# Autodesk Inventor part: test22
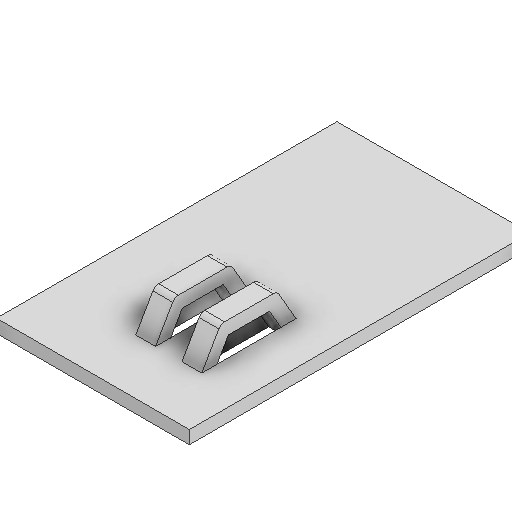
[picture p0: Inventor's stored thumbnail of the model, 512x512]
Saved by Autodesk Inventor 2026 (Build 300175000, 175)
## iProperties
Created: 2025-08
Part Number: test22
Material: Generic
Document SubType Name: Sheet Metal
Designer: sup1
Density: 1 g/cm^3
Sheet Metal Rule: Default
Appearance: Default
Author: sup1
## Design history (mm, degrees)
node "Face1"
  sketch "Sketch1"
    geometry: L1 (14.151, 25.813)-(-15.097, 25.813); L2 (-15.097, 25.813)-(-15.097, -25.813); L3 (-15.097, -25.813)-(14.151, -25.813); L4 (14.151, -25.813)-(14.151, 25.813)
    constraints: 8 end point, 2 parallel, 1 horizontal, 1 perpendicular
sketch "Sketch2"
  geometry: L1 (8.62, -16.305)-(5.62, -16.305); L2 (5.62, -16.305)-(5.62, -4.305); L3 (5.62, -4.305)-(8.62, -4.305); L4 (8.62, -4.305)-(8.62, -16.305); L5 (8.62, -16.305)-(5.62, -4.305); L6 (5.62, -16.305)-(8.62, -4.305); L7 (1.62, -4.305)-(-1.38, -4.305); L8 (-1.38, -4.305)-(-1.38, -16.305); L9 (-1.38, -16.305)-(1.62, -16.305); L10 (1.62, -16.305)-(1.62, -4.305); L11 (1.62, -4.305)-(-1.38, -16.305); L12 (-1.38, -4.305)-(1.62, -16.305); 3 further points
  constraints: 24 end point, 4 midpoint, 4 parallel, 2 equal length, 2 horizontal, 2 perpendicular
  dimensions: "Length" = 12 distance of L3.end L1.start; "d2" = 3.5 distance of point (7.12, -10.305) point (3.62, -10.305) (= 0.5 x Gap + 0.5 x Slot); "d3" = 3 distance of L1.start L1.end (= Slot); "d4" = 3.5 distance of point (0.12, -10.305) point (3.62, -10.305) (= d2); "d5" = 6 distance from line of L9 point (3.62, -10.305) (= 0.5 x Length); "d6" = 6 distance from line of L3 point (3.62, -10.305) (= d5)
extrude "Extrusion1" cut sketch "Sketch2" distance "d7" = 2 (= Thickness); taper "d8" = 0 deg
workplane "Work Plane1"
sketch "Sketch3"
  geometry: L1 (12, -2)-(13.732, -1); L2 (13.732, -1)-(10.268, 5); L3 (10.268, 5)-(1.732, 5); L4 (1.732, 5)-(-1.732, -1); L5 (-1.732, -1)-(0, -2); L6 (0, -2)-(2.887, 3); L7 (2.887, 3)-(9.113, 3); L8 (9.113, 3)-(12, -2); L9 (12, 0)-(0, 0) reference; 2 further points
  constraints: 16 end point, 4 parallel, 2 perpendicular, 1 midpoint
  dimensions: "d9" = 2 distance between parallel lines of L6 L4 (= Thickness); "d10" = 2 distance between parallel lines of L8 L2 (= Thickness); "d11" = 6 horizontal distance of point (6, 0) L5.end (= d5); "d12" = 6 horizontal distance of point (6, 0) L1.start (= d6); "d13" = 2 distance from line of L1.start L9 (= Thickness); "d14" = 2 distance from line of L9 L5.end (= Thickness); "Angle" = 60 deg angle of L6 L9; "d16" = 60 deg angle of L8 L9 (= Angle); "Height" = 5 distance between parallel lines of L9 L3; "d20" = 3 distance between parallel lines of L9 L7 (= Height - Thickness)
extrude "Extrusion2" join sketch "Sketch3" stored distance "d21" = 3 (= Slot); taper "d22" = 0 deg
fillet "Fillet1" dims "d26" = 1 (= 0.5 x Thickness)
pattern_linear "Rectangular Pattern1" dims "d25" = 7 (= Width - Slot)
body "Solid1"
face "Plate1" dims "d0" = 2 (= Thickness)
other parameters: "Thickness" = 2 (derived), "BendRadius" = 2 (= Thickness), "BendReliefWidth" = 2 (= Thickness), "BendReliefDepth" = 1 (= 0.5 x Thickness), "CornerReliefSize" = 8 (= 4 x Thickness), "SeamGap" = 0.00508, "MinimumRemnant" = 4 (= 2 x Thickness), "TransitionRadius" = 2 (= BendRadius), "JacobiRadiusSize" = 2 (= BendRadius), "GapSize" = 2 (= Thickness), "Gap" = 4 [user parameter; used in 2 equation terms], "Slot" = 3 (= -0.5 x Gap + 0.5 x Width) [user parameter; used in 4 equation terms]
